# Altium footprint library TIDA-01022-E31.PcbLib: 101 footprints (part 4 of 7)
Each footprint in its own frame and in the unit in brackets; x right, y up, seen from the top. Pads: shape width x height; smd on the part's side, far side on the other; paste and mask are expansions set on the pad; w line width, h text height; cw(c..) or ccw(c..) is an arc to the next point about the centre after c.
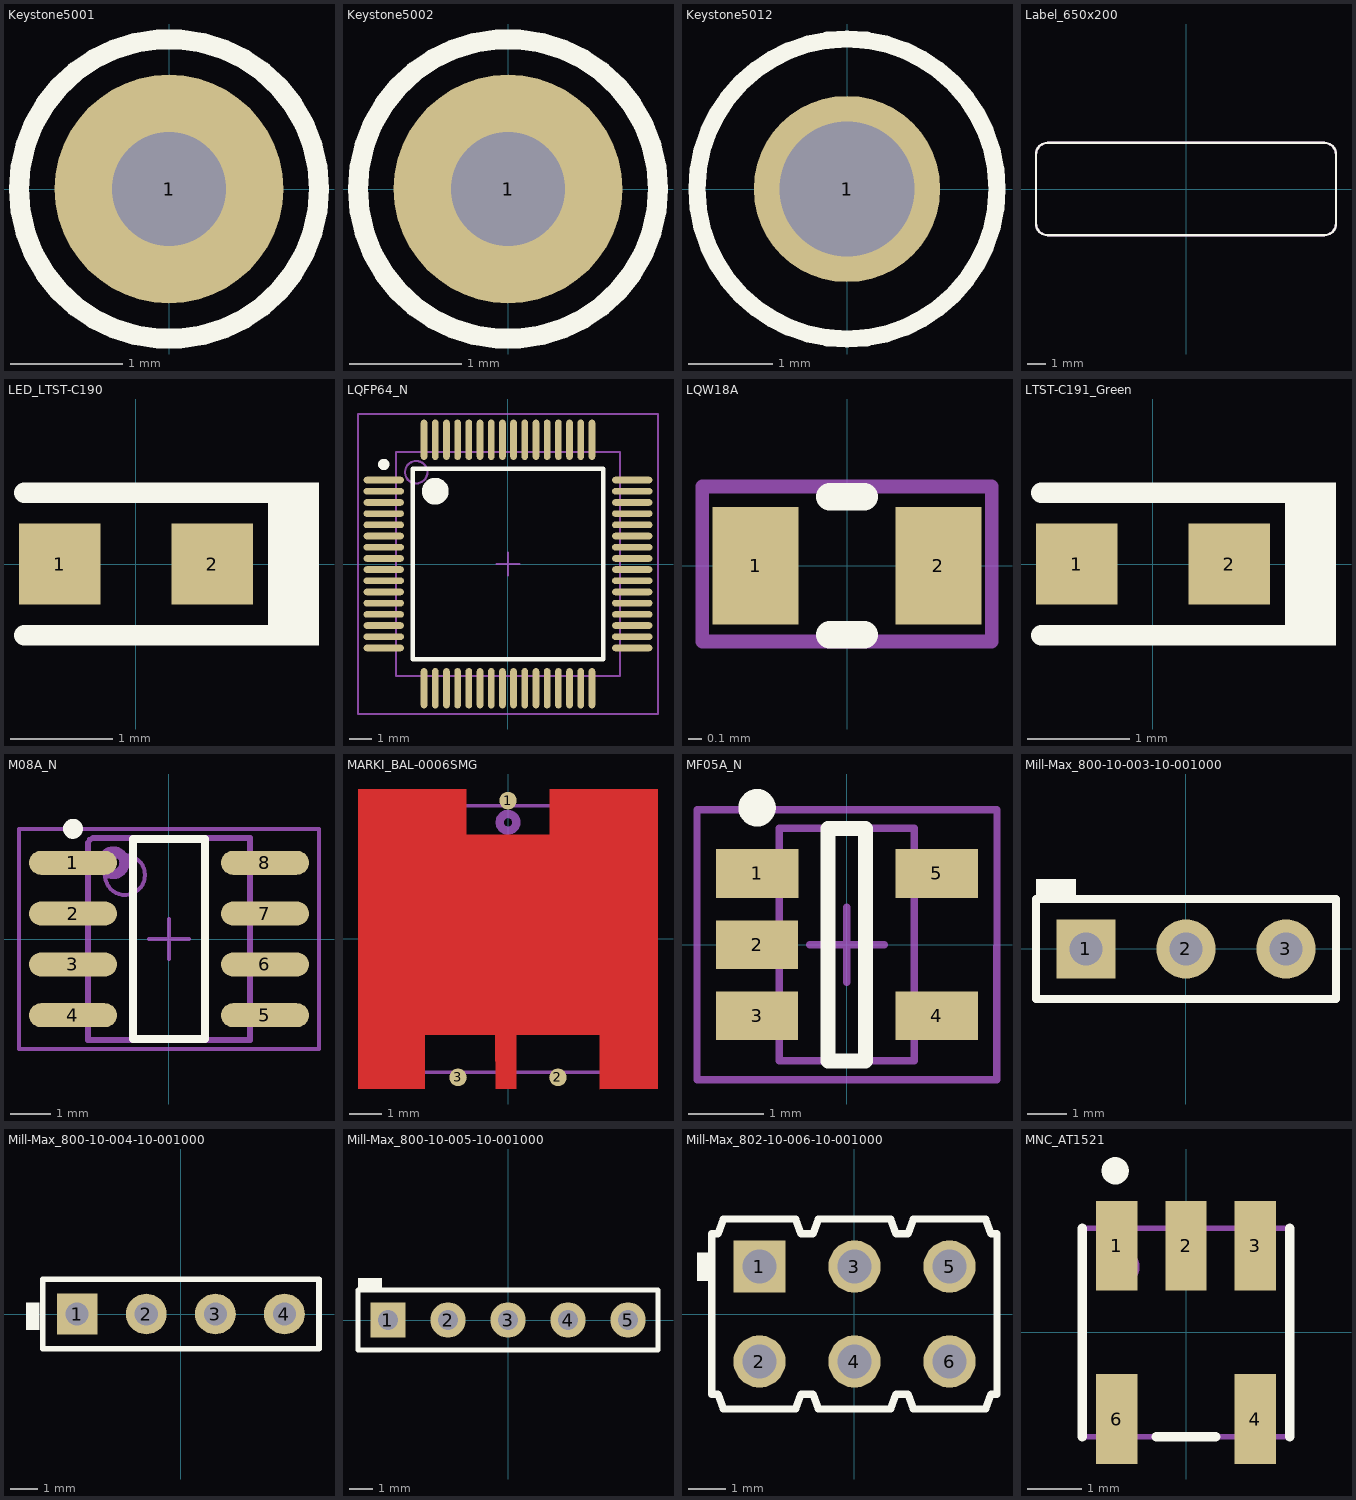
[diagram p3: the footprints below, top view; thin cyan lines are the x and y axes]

## Keystone5001 [mil] "For Keystone 500x miniature loop terminals"
height 181.1
pads (1):
  round 80 hole 40: 1(0,0)
Top Overlay:
  circle w7: c0,0 r52.5
Mechanical 5:
  circle w3.94: c0,0 r52.5
  text ".Designator" at -11.53,31 h20
3D body "Keystone_5001.stp": height 181.97, standoff -118.11, extent -49,-49 49.04,49.24

## Keystone5002 [mil] "For Keystone 500x miniature loop terminals"
height 181.1
pads (1):
  round 80 hole 40: 1(0,0)
Top Overlay:
  circle w7: c0,0 r52.5
Mechanical 5:
  circle w3.94: c0,0 r52.5
  text ".Designator" at -13.44,-5.92 h20
3D body "Keystone_5002.stp": height 181.97, standoff -118.11, extent -49,-49 49.04,49.23

## Keystone5012 [mil] "Keystone Multipurpose loops"
height 320
pads (1):
  round 87 hole 63: 1(0,0)
Top Overlay:
  circle w7.99: c0,0 r70
Mechanical 5:
  circle w5: c0,0 r69.46
  text ".Designator" at 13.8,-38.82 h20
3D body "Keystone_5012.stp": height 318.9, standoff -125.98, extent -63,-63 62.74,62.49

## Label_650x200 [mil] "Thermal Transfer Label"
height 1
pads (1):
  round 1 on Mech13: 0(0,0)
Top Overlay:
  lines w5: -325,-75 ccw(c-300,-75) -300,-100 300,-100 ccw(c300,-75) 325,-75 325,75 ccw(c300,75) 300,100 -300,100 ccw(c-300,75) -325,75 -325,-75
Mechanical 5:
  lines w5: -325,-75 ccw(c-300,-75) -300,-100 300,-100 ccw(c300,-75) 325,-75 325,75 ccw(c300,75) 300,100 -300,100 ccw(c-300,75) -325,75 -325,-75
  text ".Designator" at 18,-9 h20
3D body: height 1, standoff 0, extent -325.02,-100.02 325.02,100.02

## LED_LTST-C190 [mm] "Lite-On"
height 0.9
pads (2):
  rect 0.8x0.8 smd: 1(-0.75,0) 2(0.75,0)
Top Overlay:
  region: 1.8,0.8 1.3,0.8 1.3,-0.8 1.8,-0.8
  lines w0.2: -1.1,-0.7 1.4,-0.7 ; -1.1,0.7 1.4,0.7
Mechanical 5:
  region: 1.8,0.75 1.3,0.75 1.3,-0.75 1.8,-0.75
  lines w0.1: -1.1,-0.7 1.4,-0.7 ; -1.1,0.7 1.4,0.7
  text ".Designator" at -0.338,0.328 h0.51
3D body "Lite-On_LTST_C190.stp": height 0.9, standoff 0, extent -0.85,-0.45 0.85,0.45

## LQFP64_N [mm] "Thin QFP, 64-Leads, Body 10x10mm, Pitch 0.5mm, IPC Medium Density"
height 1.6
pads (64):
  oval 1.8x0.3 smd: 1(-5.55,3.75) 2(-5.55,3.25) 3(-5.55,2.75) 4(-5.55,2.25) 5(-5.55,1.75) 6(-5.55,1.25) 7(-5.55,0.75) 8(-5.55,0.25) 9(-5.55,-0.25) 10(-5.55,-0.75) 11(-5.55,-1.25) 12(-5.55,-1.75) 13(-5.55,-2.25) 14(-5.55,-2.75) 15(-5.55,-3.25) 16(-5.55,-3.75) 33(5.55,-3.75) 34(5.55,-3.25) 35(5.55,-2.75) 36(5.55,-2.25) 37(5.55,-1.75) 38(5.55,-1.25) 39(5.55,-0.75) 40(5.55,-0.25) 41(5.55,0.25) 42(5.55,0.75) 43(5.55,1.25) 44(5.55,1.75) 45(5.55,2.25) 46(5.55,2.75) 47(5.55,3.25) 48(5.55,3.75)
  oval 0.3x1.8 smd: 17(-3.75,-5.55) 18(-3.25,-5.55) 19(-2.75,-5.55) 20(-2.25,-5.55) 21(-1.75,-5.55) 22(-1.25,-5.55) 23(-0.75,-5.55) 24(-0.25,-5.55) 25(0.25,-5.55) 26(0.75,-5.55) 27(1.25,-5.55) 28(1.75,-5.55) 29(2.25,-5.55) 30(2.75,-5.55) 31(3.25,-5.55) 32(3.75,-5.55) 49(3.75,5.55) 50(3.25,5.55) 51(2.75,5.55) 52(2.25,5.55) 53(1.75,5.55) 54(1.25,5.55) 55(0.75,5.55) 56(0.25,5.55) 57(-0.25,5.55) 58(-0.75,5.55) 59(-1.25,5.55) 60(-1.75,5.55) 61(-2.25,5.55) 62(-2.75,5.55) 63(-3.25,5.55) 64(-3.75,5.55)
Top Overlay:
  circle w0.6: c-3.25,3.25 r0.3
  circle w0.25: c-5.55,4.45 r0.125
  lines w0.2: -4.25,-4.25 4.25,-4.25 4.25,4.25 -4.25,4.25 -4.25,-4.25
Mechanical 5:
  circle w0.1: c-4.1,4.1 r0.5
  lines w0.1: -5,-5 5,-5 5,5 -5,5 -5,-5
  text ".Designator" at 0.955,0.445 h0.51
Mechanical 15:
  lines w0.1: -0.5,0 0.5,0 ; 0,-0.5 0,0.5 ; -6.7,-6.7 6.7,-6.7 6.7,6.7 -6.7,6.7 -6.7,-6.7
3D body: height 1.6, standoff 0, extent -5,-5 5,5

## LQW18A [mm] "Murata"
height 1
pads (2):
  rect 0.625x0.85 smd: 1(-0.663,0) 2(0.663,0)
Top Overlay:
  lines w0.2: -0.125,-0.5 0.125,-0.5 ; -0.125,0.5 0.125,0.5
Mechanical 5:
  lines w0.1: -1.05,-0.55 -1.05,0.575 1.05,0.575 1.05,-0.55 -1.05,-0.55
  text ".Designator" at -0.44,-0.231 h0.51
3D body: height 1, standoff 0.75, extent -0.899,-0.499 0.899,0.499
3D body: height 0.75, standoff 0.4, extent -0.899,-0.499 0.899,0.499
3D body: height 0.4, standoff 0.3, extent 0.476,-0.474 0.874,0.474
3D body: height 0.4, standoff 0.3, extent -0.849,-0.474 -0.451,0.474
3D body: height 0.3, standoff 0, extent 0.476,-0.474 0.874,0.474
3D body: height 0.3, standoff 0, extent -0.849,-0.474 -0.451,0.474

## LTST-C191_Green [mm] "Lite-On"
height 0.65
pads (2):
  rect 0.8x0.8 smd: 1(-0.75,0) 2(0.75,0)
Top Overlay:
  region: 1.8,0.8 1.3,0.8 1.3,-0.8 1.8,-0.8
  lines w0.2: -1.1,-0.7 1.4,-0.7 ; -1.1,0.7 1.4,0.7
Mechanical 5:
  region: 1.8,0.75 1.3,0.75 1.3,-0.75 1.8,-0.75
  lines w0.1: -1.1,-0.7 1.4,-0.7 ; -1.1,0.7 1.4,0.7
  text ".Designator" at 0.702,0.162 h0.51
3D body: height 0.65, standoff 0.2, extent -0.624,-0.449 0.624,0.449
3D body: height 0.2, standoff 0, extent -0.849,-0.449 0.849,0.449

## M08A_N [mm] "SOIC, 8-Leads, Body 4.9x3.9mm, Pitch 1.27mm, IPC Medium Density"
height 1.75
pads (8):
  oval 2.2x0.6 smd: 1(-2.4,1.905) 2(-2.4,0.635) 3(-2.4,-0.635) 4(-2.4,-1.905) 5(2.4,-1.905) 6(2.4,-0.635) 7(2.4,0.635) 8(2.4,1.905)
Top Overlay:
  circle w0.25: c-2.4,2.755 r0.125
  lines w0.2: -0.9,-2.5 0.9,-2.5 0.9,2.5 -0.9,2.5 -0.9,-2.5
Mechanical 5:
  circle w0.254: c-1.397,1.905 r0.284
  lines w0.127: -2.032,-2.54 -2.032,2.413 -1.905,2.54 2.032,2.54 2.032,-2.54 -2.032,-2.54
  text ".Designator" at -1.524,-0.508 h0.51
Mechanical 13:
  circle w0.1: c-1.1,1.6 r0.5
  lines w0.1: -2,-2.5 2,-2.5 2,2.5 -2,2.5 -2,-2.5
Mechanical 15:
  lines w0.1: -0.5,0 0.5,0 ; 0,-0.5 0,0.5 ; -3.75,-2.75 3.75,-2.75 3.75,2.75 -3.75,2.75 -3.75,-2.75
3D body: height 1.75, standoff 0, extent -2,-2.5 2,2.5

## MARKI_BAL-0006SMG [mil] "SMD, 3-Leads, Body 320x320mil"
height 155
pads (3):
  round 21 smd: 1(0,166) 2(60,-166) 3(-60,-166)
Top Layer:
  region: -100,-180 -100,-115 -15,-115 -15,-180 10,-180 10,-115 110.01,-115.01 109.99,-180 180,-180 180,180 50,180 50,125 -50,125 -50,180 -180,180 -180,-180
Mechanical 5:
  circle w10: c0,140 r10
  lines w3.94: -160,-160 -160,160 160,160 160,-160 -160,-160
  text ".Designator" at 46.58,-1.98 h20
3D body "BAL-0006SMG.stp": height 155, standoff 0, extent -160,-160 160,160

## MF05A_N [mm] "SOT23, 5-Leads, Body 2.9x1.6mm, Pitch 0.95mm, Lead Span 2.8mm, IPC Medium Density"
height 1.19
pads (5):
  rect 1.1x0.65 smd: 1(-1.2,0.95) 2(-1.2,0) 3(-1.2,-0.95) 4(1.2,-0.95) 5(1.2,0.95)
Top Overlay:
  circle w0.25: c-1.2,1.825 r0.125
  lines w0.2: -0.25,-1.55 0.25,-1.55 0.25,1.55 -0.25,1.55 -0.25,-1.55
Mechanical 5:
  text ".Designator" at -0.622,-0.178 h0.51
Mechanical 13:
  lines w0.1: -0.9,-1.55 -0.9,1.55 0.9,1.55 0.9,-1.55 -0.9,-1.55
Mechanical 15:
  lines w0.1: -0.5,0 0.5,0 ; 0,-0.5 0,0.5 ; -2,-1.8 -2,1.8 2,1.8 2,-1.8 -2,-1.8
3D body: height 1.19, standoff 0, extent -0.9,-1.55 0.9,1.55

## Mill-Max_800-10-003-10-001000 [mm] "Mill-Max"
height 8.128
pads (3):
  rect 1.5x1.5 hole 0.85: 1(-2.54,0)
  round 1.5 hole 0.85: 2(0,0) 3(2.54,0)
Top Overlay:
  rectangle: -3.81,1.27 -2.794,1.778
  lines w0.203: -3.81,-1.27 3.81,-1.27 3.81,1.27 -3.81,1.27 -3.81,-1.27
Mechanical 5:
  lines w0.102: -3.81,-1.27 -3.81,1.27 3.81,1.27 3.81,-1.27 -3.81,-1.27
  text ".Designator" at 0.862,-0.726 h0.51
3D body: height 8.13, standoff 0, extent 2.162,-0.38 2.921,0.38
3D body: height 8.13, standoff 0, extent -0.378,-0.38 0.381,0.38
3D body: height 8.13, standoff 0, extent -2.918,-0.38 -2.159,0.38
3D body: height 0.81, standoff -3, extent 2.238,-0.304 2.845,0.304
3D body: height 0.81, standoff -3, extent -0.302,-0.304 0.305,0.304
3D body: height 0.81, standoff -3, extent -2.842,-0.304 -2.235,0.304
3D body: height 3.17, standoff 0, extent -3.809,-1.269 3.809,1.269

## Mill-Max_800-10-004-10-001000 [mm] "Mill-Max"
height 8.128
pads (4):
  rect 1.5x1.5 hole 0.85: 1(-3.81,0)
  round 1.5 hole 0.85: 2(-1.27,0) 3(1.27,0) 4(3.81,0)
Top Overlay:
  region: -5.186,-0.596 -5.186,0.42 -5.694,0.42 -5.694,-0.596
  lines w0.203: -5.08,-1.27 -5.08,1.27 5.08,1.27 5.08,-1.27 -5.08,-1.27
Mechanical 5:
  lines w0.102: -5.08,-1.27 5.08,-1.27 5.08,1.27 -5.08,1.27 -5.08,-1.27
  text ".Designator" at 0.206,-0.787 h0.51
3D body: height 0.81, standoff -3, extent -4.112,-0.304 -3.505,0.304
3D body: height 0.81, standoff -3, extent -1.572,-0.304 -0.965,0.304
3D body: height 0.81, standoff -3, extent 0.968,-0.304 1.575,0.304
3D body: height 0.81, standoff -3, extent 3.508,-0.304 4.115,0.304
3D body: height 8.13, standoff 0, extent -4.188,-0.38 -3.429,0.38
3D body: height 8.13, standoff 0, extent -1.648,-0.38 -0.889,0.38
3D body: height 8.13, standoff 0, extent 0.892,-0.38 1.651,0.38
3D body: height 8.13, standoff 0, extent 3.432,-0.38 4.191,0.38
3D body: height 3.17, standoff 0, extent -5.079,-1.269 5.079,1.269

## Mill-Max_800-10-005-10-001000 [mm] "Mill-Max"
height 8.128
pads (5):
  rect 1.5x1.5 hole 0.85: 1(-5.08,0)
  round 1.5 hole 0.85: 2(-2.54,0) 3(0,0) 4(2.54,0) 5(5.08,0)
Top Overlay:
  rectangle: -6.35,1.27 -5.334,1.778
  lines w0.203: -6.35,-1.27 -6.35,1.27 6.35,1.27 6.35,-1.27 -6.35,-1.27
Mechanical 5:
  lines w0.102: -6.35,-1.27 6.35,-1.27 6.35,1.27 -6.35,1.27 -6.35,-1.27
  text ".Designator" at 1.651,0.025 h0.51
3D body: height 3.17, standoff 0, extent -6.349,-1.269 6.349,1.269
3D body: height 0.81, standoff -3, extent -5.382,-0.304 -4.775,0.304
3D body: height 0.81, standoff -3, extent -2.842,-0.304 -2.235,0.304
3D body: height 0.81, standoff -3, extent -0.302,-0.304 0.305,0.304
3D body: height 0.81, standoff -3, extent 2.238,-0.304 2.845,0.304
3D body: height 0.81, standoff -3, extent 4.778,-0.304 5.385,0.304
3D body: height 8.13, standoff 0, extent -5.458,-0.38 -4.699,0.38
3D body: height 8.13, standoff 0, extent -2.918,-0.38 -2.159,0.38
3D body: height 8.13, standoff 0, extent -0.378,-0.38 0.381,0.38
3D body: height 8.13, standoff 0, extent 2.162,-0.38 2.921,0.38
3D body: height 8.13, standoff 0, extent 4.702,-0.38 5.461,0.38

## Mill-Max_802-10-006-10-001000 [mm] "Header, 2.54 mm, 3x2, TH"
height 8.13
pads (6):
  rect 1.4x1.4 hole 0.9: 1(-2.54,1.27)
  round 1.4 hole 0.9: 2(-2.54,-1.27) 3(0,1.27) 4(0,-1.27) 5(2.54,1.27) 6(2.54,-1.27)
Top Overlay:
  rectangle: -4.211,0.888 -3.855,1.65
  lines w0.2: -3.81,-2.14 -3.81,2.14 -3.65,2.14 -3.505,2.54 -1.576,2.54 -1.43,2.14 -1.11,2.14 -0.965,2.54 0.964,2.54 1.11,2.14 1.43,2.14 1.575,2.54 3.504,2.54 3.65,2.14 3.81,2.14 3.81,-2.14 3.65,-2.14 3.504,-2.54 1.575,-2.54 1.43,-2.14 1.11,-2.14 0.964,-2.54 -0.965,-2.54 -1.11,-2.14 -1.43,-2.14 -1.576,-2.54 -3.505,-2.54 -3.65,-2.14 -3.81,-2.14
Mechanical 5:
  lines w0.1: -3.81,-2.14 -3.65,-2.14 -3.505,-2.54 -1.576,-2.54 -1.43,-2.14 -1.11,-2.14 -0.965,-2.54 0.964,-2.54 1.11,-2.14 1.43,-2.14 1.575,-2.54 3.504,-2.54 3.65,-2.14 3.81,-2.14 3.81,2.14 3.65,2.14 3.504,2.54 1.575,2.54 1.43,2.14 1.11,2.14 0.964,2.54 -0.965,2.54 -1.11,2.14 -1.43,2.14 -1.576,2.54 -3.505,2.54 -3.65,2.14 -3.81,2.14 -3.81,-2.14
  text ".Designator" at 0.94,0.025 h0.51
3D body "mill-max-802-10-006-10-001000.stp": height 8.11, standoff -3.02, extent -3.846,-2.54 3.774,2.54

## MNC_AT1521 [mm] "SMD, 5-leads, Body 3.81x3.81mm, Pitch 1.27mm"
height 4.06
pads (5):
  rect 0.76x1.65 smd: 1(-1.27,1.59) 2(0,1.59) 3(1.27,1.59) 4(1.27,-1.59) 6(-1.27,-1.59)
Top Overlay:
  circle w0.25: c-1.3,2.965 r0.125
  lines w0.178: -1.905,-1.913 -1.905,1.913 ; -0.547,-1.913 0.547,-1.913 ; 1.905,-1.913 1.905,1.913
Mechanical 5:
  circle w0.1: c-1.2,1.2 r0.3
  lines w0.1: -1.905,-1.913 1.905,-1.913 1.905,1.913 -1.905,1.913 -1.905,-1.913
  text ".Designator" at 0.3,-0.404 h0.51
3D body: height 4.06, standoff 0, extent -1.905,-1.913 1.905,1.913
3D body: height 4.07, standoff 4.06, extent -1.499,0.901 -0.901,1.499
